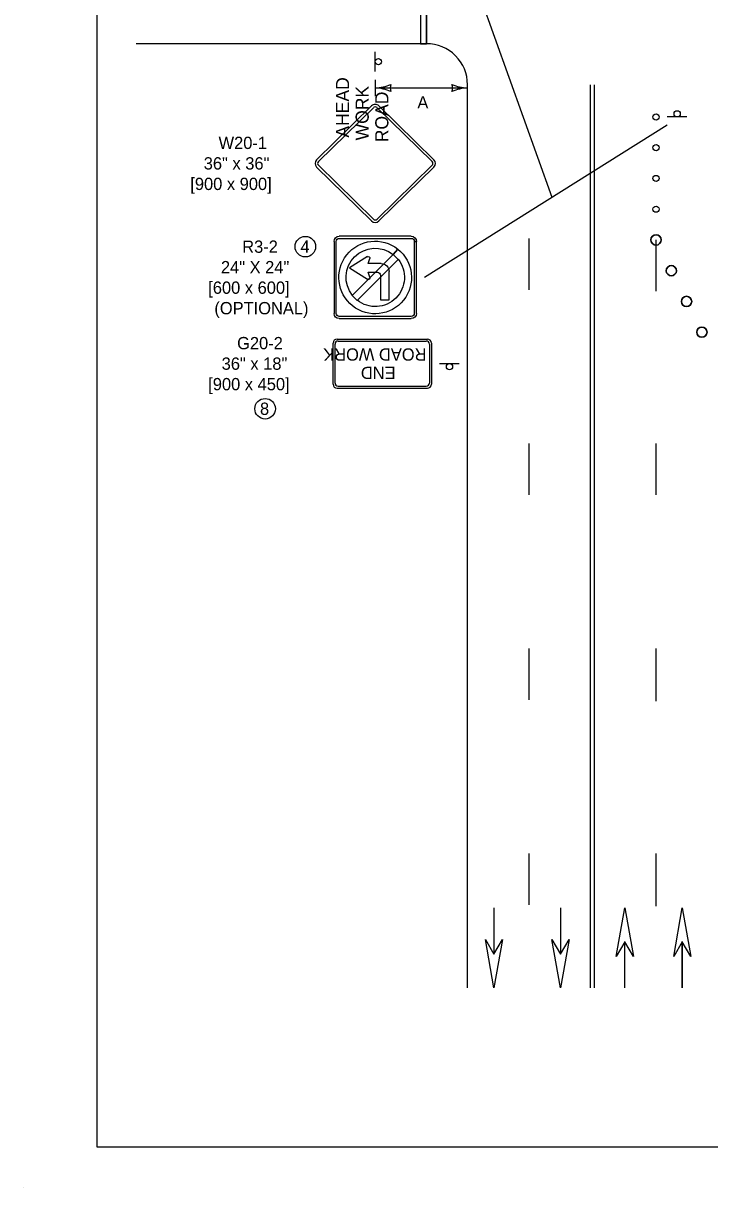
# Model space of a CAD drawing. Extents: x 49991.4 to 50021, y 49987.6 to 50011.4.
# Drawn here: x 49999.98 to 50003.32, y 49999.86 to 50005.54 of the extents above; entities that cross this region are included whole.
import ezdxf

# ---------------------------------------------------------------- set-up
doc = ezdxf.new("R2010")
doc.units = 0
for name, color, linetype in [('Level 1', 7, 'Continuous'), ('Level 2', 7, 'Continuous'), ('Level 25', 7, 'Continuous'), ('Level 3', 7, 'Continuous')]:
    doc.layers.add(name, color=color, linetype=linetype)

# ---------------------------------------------------------------- blocks, each defined once
blk = doc.blocks.new('R3.1')
at = {"layer": 'Level 25'}
for p, q in [((-35.8, 39.5), (38.3, 39.5)), ((38.3, 37.3), (-35.8, 37.3)), ((-41.1, 34.2), (-38.9, 34.2)), ((-38.9, 34.2), (-41.1, 34.2)), ((-41.1, -39.9), (-41.1, 34.2)), ((-41.1, 34.2), (-38.9, 34.2)), ((-38.9, 34.2), (-38.9, -39.9)), ((-21.9, 26.2), (-17.3, 20.7)), ((-17.2, 20.8), (-21.8, 26.3)), ((41.4, -39.9), (41.4, 34.2)), ((43.6, 34.2), (43.6, -39.9)), ((-17.3, 20.7), (-22.3, 15.7)), ((-17.3, 20.7), (-22.3, 15.7)), ((-22.3, 15.7), (19.8, -26.4)), ((24.8, -21.4), (-17.3, 20.7)), ((8.4, 11.3), (6.7, 16.5)), ((9.3, 18.5), (27.7, 6.9)), ((9.3, 18.5), (9.3, 18.5)), ((-12.9, -25.7), (-12.9, 3.3)), ((-4.9, 11.3), (8.4, 11.3)), ((8.4, 2.5), (-1.1, 2.5)), ((6.7, -2.7), (8.4, 2.5)), ((27.7, 6.9), (9.3, -4.7)), ((-4.1, -0.5), (-4.1, -25.7)), ((19.8, -26.4), (24.8, -21.4)), ((19.8, -26.4), (24.8, -21.4)), ((-4.1, -25.7), (-12.9, -25.7)), ((-35.8, -42.9), (38.3, -42.9)), ((38.3, -45.2), (-35.8, -45.2))]:
    blk.add_line(p, q, dxfattribs=at)
for centre, radius, start, end in [((-35.8, 34.2), 5.29, 90, 180), ((-35.8, 34.2), 3.09, 90, 180), ((38.3, 34.2), 5.29, 0, 90), ((38.3, 34.2), 3.09, 0, 90), ((1.3, -2.9), 37.3, 128.573, 128.3407), ((1.2, -2.8), 30, 321.7571, 127.9547), ((1.2, -2.8), 30, 141.7565, 308.2429), ((8.4, 17), 1.75, 57.757, 197.6186), ((1.2, -2.8), 30, 44.2869, 44.4163), ((-4.9, 3.3), 8, 90, 180), ((-1.1, -0.5), 3, 90, 180), ((8.4, -3.2), 1.75, 162.3804, 302.2438), ((1.2, -2.8), 30, 220.8564, 220.8714), ((-35.8, -39.9), 5.29, 180, 270), ((-35.8, -39.9), 3.09, 180, 270), ((38.3, -39.9), 5.29, 270, 0), ((38.3, -39.9), 3.09, 270, 0)]:
    blk.add_arc(centre, radius, start, end, dxfattribs=at)

msp = doc.modelspace()

# ---------------------------------------------------------------- linework, layer by layer
at = {"layer": 'Level 1'}
for p, q in [((50001.9135, 50005.7527), (50001.9135, 50005.4426)), ((50001.9435, 50005.7527), (50001.9435, 50005.4426)), ((50001.9435, 50005.4426), (50000.5266, 50005.4426)), ((50001.6935, 50005.3066), (50001.6935, 50005.4026)), ((50002.1435, 50000.8367), (50002.1435, 50005.2426)), ((50002.7435, 50000.8367), (50002.7435, 50005.2426)), ((50002.7635, 50000.8367), (50002.7635, 50005.2426)), ((50001.4076, 50004.8768), (50001.6756, 50005.1393)), ((50001.4162, 50004.868), (50001.6842, 50005.1305)), ((50001.7029, 50005.1305), (50001.9708, 50004.868)), ((50001.7115, 50005.1393), (50001.9794, 50004.8768)), ((50003.2141, 50005.0853), (50003.1181, 50005.0853)), ((50001.6756, 50004.5783), (50001.4076, 50004.8408)), ((50001.6842, 50004.5871), (50001.4162, 50004.8496)), ((50001.9708, 50004.8496), (50001.7029, 50004.5871)), ((50001.9794, 50004.8408), (50001.7115, 50004.5783)), ((50002.4436, 50004.2426), (50002.4436, 50004.4926)), ((50003.0381, 50004.4853), (50003.0381, 50004.4853)), ((50003.0631, 50004.2353), (50003.0631, 50004.4853)), ((50001.5076, 50004.002), (50001.9476, 50004.002)), ((50001.5125, 50003.992), (50001.9425, 50003.992)), ((50001.4875, 50003.782), (50001.4875, 50003.982)), ((50001.4975, 50003.787), (50001.4975, 50003.977)), ((50001.9575, 50003.977), (50001.9575, 50003.787)), ((50001.9675, 50003.982), (50001.9675, 50003.782)), ((50002.0075, 50003.882), (50002.1035, 50003.882)), ((50001.5075, 50003.762), (50001.9475, 50003.762)), ((50001.5125, 50003.772), (50001.9425, 50003.772)), ((50002.4436, 50003.2426), (50002.4436, 50003.4926)), ((50003.0636, 50003.2426), (50003.0636, 50003.4926)), ((50002.4436, 50002.2426), (50002.4436, 50002.4926)), ((50002.4436, 50002.2426), (50002.4436, 50002.4926)), ((50003.0631, 50002.2353), (50003.0631, 50002.4853)), ((50003.0636, 50002.2426), (50003.0636, 50002.4926)), ((50003.0636, 50002.2426), (50003.0636, 50002.4926)), ((50002.4436, 50001.2426), (50002.4436, 50001.4926)), ((50002.4436, 50001.2426), (50002.4436, 50001.4926)), ((50003.0631, 50001.2353), (50003.0631, 50001.4853)), ((50003.0636, 50001.2426), (50003.0636, 50001.4926)), ((50003.0636, 50001.2426), (50003.0636, 50001.4926)), ((50002.2722, 50001.2268), (50002.2722, 50001.0009)), ((50002.2726, 50001.2268), (50002.2726, 50001.0009)), ((50002.5969, 50001.2268), (50002.5969, 50001.0009)), ((50002.5973, 50001.2268), (50002.5973, 50001.0009)), ((50002.9105, 50000.8367), (50002.9105, 50001.0626)), ((50002.9109, 50000.8367), (50002.9109, 50001.0626)), ((50003.1911, 50000.8367), (50003.1911, 50001.0626)), ((50003.1915, 50000.8367), (50003.1915, 50001.0626)), ((49999.9766, 49999.8624), (49999.9766, 49999.8624))]:
    msp.add_line(p, q, dxfattribs=at)
for points in [[(50008.6146, 50011.2628), (50000.3356, 50011.2628), (50000.3356, 50000.0624), (50008.6146, 50000.0624)], [(50002.8689, 50000.9903), (50002.9105, 50001.2268), (50002.9525, 50000.9903), (50002.9105, 50001.0625)], [(50003.1495, 50000.9903), (50003.1911, 50001.2268), (50003.2331, 50000.9903), (50003.1911, 50001.0625)], [(50002.3142, 50001.0732), (50002.2726, 50000.8367), (50002.2306, 50001.0732), (50002.2726, 50001.001)], [(50002.6389, 50001.0732), (50002.5973, 50000.8367), (50002.5553, 50001.0732), (50002.5973, 50001.001)]]:
    msp.add_lwpolyline(points, close=True, dxfattribs=at)
msp.add_lwpolyline([(50001.9135, 50005.4426), (50001.9435, 50005.4426), (50001.9435, 50005.7427), (50001.9135, 50005.7427), (50001.9135, 50005.4426)], dxfattribs=at)
for centre, radius in [((50001.7086, 50005.3547), 0.0152), ((50003.0631, 50005.0853), 0.015), ((50003.1661, 50005.1005), 0.0152), ((50003.0631, 50004.9353), 0.015), ((50003.0631, 50004.7853), 0.015), ((50003.0631, 50004.6353), 0.015), ((50003.0631, 50004.4853), 0.025), ((50003.1377, 50004.3353), 0.025), ((50003.2122, 50004.1853), 0.025), ((50003.2868, 50004.0353), 0.025), ((50002.0555, 50003.8668), 0.0152)]:
    msp.add_circle(centre, radius, dxfattribs=at)
for centre, radius, start, end in [((50001.9435, 50005.2426), 0.2, 359.9999, 90), ((50003.0631, 50004.4853), 0.025, 0, 180), ((50003.0631, 50004.4853), 0.025, 180, 0), ((50003.1377, 50004.3353), 0.025, 0, 180), ((50003.1377, 50004.3353), 0.025, 180, 0), ((50003.2122, 50004.1853), 0.025, 0, 180), ((50003.2122, 50004.1853), 0.025, 180, 0), ((50003.2868, 50004.0353), 0.025, 0, 180), ((50001.5076, 50003.982), 0.02, 90, 180), ((50001.5125, 50003.977), 0.015, 90, 180), ((50001.9425, 50003.977), 0.015, 360, 90), ((50001.9476, 50003.982), 0.02, 360, 90), ((50003.2868, 50004.0353), 0.025, 180, 0), ((50001.5075, 50003.782), 0.02, 180, 270), ((50001.5125, 50003.787), 0.015, 180, 270), ((50001.9425, 50003.787), 0.015, 270, 360), ((50001.9475, 50003.782), 0.02, 270, 360)]:
    msp.add_arc(centre, radius, start, end, dxfattribs=at)
for centre, major_axis, ratio, start_param, end_param in [((50001.6935, 50005.1214), (0.0255, 0), 0.98963, 0.785394, 2.356194), ((50001.6935, 50005.1214), (0.0132, 0), 0.98, 0.785394, 2.356194), ((50001.4255, 50004.8588), (-0.0255, 0), 0.98963, 5.497795, 7.068583), ((50001.4255, 50004.8588), (-0.0132, 0), 0.98, 5.497795, 7.068583), ((50001.9614, 50004.8588), (0.0132, 0), 0.98, 5.497787, 7.068583), ((50001.9614, 50004.8588), (0.0255, 0), 0.98963, 5.497787, 7.068583), ((50001.6935, 50004.5962), (0.0255, 0), 0.98963, 3.926991, 5.497787), ((50001.6935, 50004.5962), (0.0132, 0), 0.98, 3.926991, 5.497787)]:
    msp.add_ellipse(centre, major_axis=major_axis, ratio=ratio, start_param=start_param, end_param=end_param, dxfattribs=at)
at = {"layer": 'Level 2'}
for centre in [(50001.3524, 50004.4527), (50001.1562, 50003.662)]:
    msp.add_circle(centre, 0.0501, dxfattribs=at)
at = {"layer": 'Level 3'}
for p, q in [((50002.5561, 50004.6926), (50002.0161, 50006.2026)), ((50001.6935, 50005.2666), (50001.6935, 50005.1866)), ((50001.6935, 50005.2266), (50002.1435, 50005.2266)), ((50003.1181, 50005.0453), (50001.9344, 50004.3025))]:
    msp.add_line(p, q, dxfattribs=at)
for centre, radius, start, end in [((50001.682, 50005.4593), 0.233, 272.8273, 292.0772), ((50001.8217, 50005.2266), 0.0548, 162.1388, 197.8612), ((50002.1526, 50005.4487), 0.2223, 247.456, 267.6395), ((50002.0153, 50005.2266), 0.0548, 342.1388, 17.8612), ((50001.6843, 50005.0045), 0.2223, 67.456, 87.6395), ((50002.155, 50004.9939), 0.233, 92.8273, 112.0772)]:
    msp.add_arc(centre, radius, start, end, dxfattribs=at)

# ---------------------------------------------------------------- block references
at = {"layer": 'Level 1', "xscale": 0.004746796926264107, "yscale": -0.004746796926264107, "rotation": 180}
msp.add_blockref('R3.1', (50001.6993, 50004.316), dxfattribs=at)

# ---------------------------------------------------------------- texts
at = {"layer": 'Level 1'}
for s, height, rotation, p in [('AHEAD', 0.06389, 90, (50001.5658, 50004.9845)), ('WORK', 0.06389, 90, (50001.6616, 50004.9709)), ('ROAD', 0.06389, 90, (50001.7574, 50004.962)), ('ROAD WORK', 0.06, 180, (50001.9433, 50003.9566)), ('END', 0.06, 180, (50001.7927, 50003.8666))]:
    msp.add_text(s, height=height, rotation=rotation, dxfattribs=at).set_placement(p)
at = {"layer": 'Level 2'}
for s, p in [('A', (50001.8989, 50005.1266)), ('W20-1', (50000.9292, 50004.9288)), ('36" x 36"', (50000.8569, 50004.8288)), ('[900 x 900]', (50000.7913, 50004.7288))]:
    msp.add_text(s, height=0.06, rotation=360, dxfattribs=at).set_placement(p)
for s, p in [('R3-2', (50001.0445, 50004.4226)), ('4', (50001.3285, 50004.4227)), ('24" X 24"', (50000.9406, 50004.3226)), ('[600 x 600]', (50000.8788, 50004.2226)), ('(OPTIONAL)', (50000.9086, 50004.1226)), ('G20-2', (50001.0196, 50003.952)), ('36" x 18"', (50000.9443, 50003.852)), ('[900 x 450]', (50000.8788, 50003.752)), ('8', (50001.1312, 50003.632))]:
    msp.add_text(s, height=0.06, dxfattribs=at).set_placement(p)

doc.saveas('drawing.dxf')
